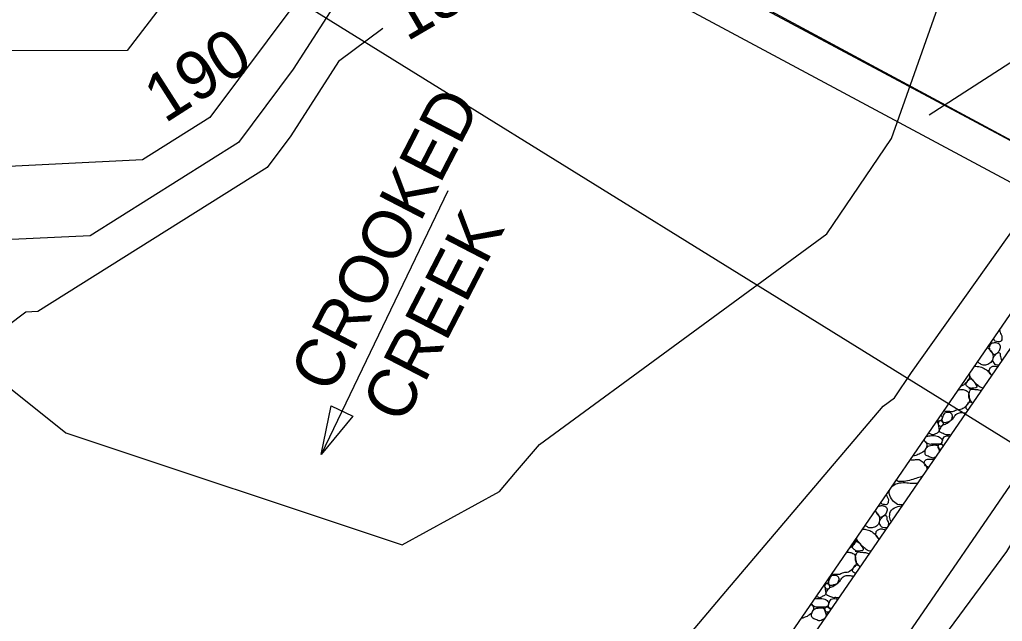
# Model space of a CAD drawing. Extents: x 1385284 to 1385995, y 1975154 to 1975620.
# Drawn here: x 1385530.9 to 1385581.7, y 1975526 to 1975557.1 of the extents above; entities that cross this region are included whole.
import ezdxf

# ---------------------------------------------------------------- set-up
doc = ezdxf.new("R2010")
doc.units = 0
for name, color, linetype in [('Default', 7, 'Continuous'), ('DTM_CONTOURS_MINOR', 7, 'Continuous'), ('R_Prop Surface', 7, 'Continuous'), ('R_Proposed Const Limits', 7, 'Continuous'), ('S_BASELINE', 7, 'Continuous'), ('S_BRIDGE', 7, 'Continuous'), ('S_UNDERGROUND_CABLE', 7, 'Continuous'), ('S_WATER_UTILITIES', 7, 'Continuous')]:
    doc.layers.add(name, color=color, linetype=linetype)

msp = doc.modelspace()

# ---------------------------------------------------------------- linework, layer by layer
at = {"layer": 'Default'}
for p, q in [((1385552.239, 1975498.351), (1385589.716, 1975552.857)), ((1385590.54, 1975552.29), (1385553.307, 1975498.139)), ((1385553.052, 1975548.241), (1385546.5, 1975534.596))]:
    msp.add_line(p, q, dxfattribs=at)
msp.add_lwpolyline([(1385548.145, 1975536.579), (1385546.5, 1975534.596), (1385547.018, 1975537.12)], close=True, dxfattribs=at)
for points in [[(1385581.715, 1975540.534), (1385581.704, 1975540.509), (1385581.656, 1975540.419), (1385581.534, 1975540.434), (1385581.355, 1975540.453), (1385581.331, 1975540.546), (1385581.303, 1975540.598), (1385581.296, 1975540.611)], [(1385581.597, 1975541.049), (1385581.6, 1975541.047), (1385581.63, 1975541.021), (1385581.615, 1975540.93), (1385581.677, 1975540.804), (1385581.759, 1975540.668), (1385581.696, 1975540.564), (1385581.715, 1975540.534)], [(1385580.975, 1975540.144), (1385581.019, 1975540.107), (1385581.16, 1975539.971), (1385581.288, 1975539.759), (1385581.25, 1975539.442), (1385581.064, 1975539.27), (1385580.895, 1975539.226), (1385580.811, 1975539.226)], [(1385581.388, 1975539.8), (1385581.357, 1975539.726), (1385581.152, 1975539.908), (1385581.05, 1975540.086), (1385581.101, 1975540.306), (1385581.265, 1975540.379), (1385581.492, 1975540.386), (1385581.682, 1975540.261), (1385581.631, 1975540.023), (1385581.518, 1975539.858), (1385581.414, 1975539.811), (1385581.388, 1975539.8)], [(1385581.557, 1975539.226), (1385581.55, 1975539.226), (1385581.493, 1975539.227), (1385581.355, 1975539.25), (1385581.317, 1975539.366), (1385581.243, 1975539.475), (1385581.282, 1975539.639), (1385581.377, 1975539.751), (1385581.454, 1975539.84), (1385581.533, 1975539.895), (1385581.658, 1975539.844), (1385581.615, 1975539.727), (1385581.676, 1975539.605), (1385581.702, 1975539.496), (1385581.712, 1975539.451)], [(1385580.305, 1975539.169), (1385580.402, 1975539.164), (1385580.602, 1975539.167), (1385580.883, 1975539.027), (1385581.071, 1975538.869), (1385581.162, 1975538.73), (1385581.186, 1975538.686)], [(1385580.811, 1975539.226), (1385580.739, 1975539.223), (1385580.603, 1975539.285), (1385580.502, 1975539.363), (1385580.462, 1975539.398)], [(1385581.187, 1975538.687), (1385581.181, 1975538.693), (1385581.118, 1975538.77), (1385581.05, 1975538.883), (1385581.101, 1975539.103), (1385581.265, 1975539.176), (1385581.42, 1975539.186), (1385581.502, 1975539.153), (1385581.506, 1975539.151)], [(1385580.035, 1975538.777), (1385580.049, 1975538.706), (1385580.077, 1975538.518), (1385579.882, 1975538.329), (1385579.736, 1975538.172), (1385579.628, 1975538.143), (1385579.595, 1975538.137)], [(1385580.736, 1975538.031), (1385580.69, 1975538.043), (1385580.54, 1975538.12), (1385580.36, 1975538.287), (1385580.156, 1975538.505), (1385580.063, 1975538.684), (1385580.031, 1975538.771)], [(1385580.128, 1975538.023), (1385580.081, 1975538.023), (1385579.985, 1975538.095), (1385579.822, 1975538.188), (1385579.931, 1975538.374), (1385579.979, 1975538.538), (1385580.16, 1975538.512), (1385580.28, 1975538.408), (1385580.347, 1975538.263), (1385580.534, 1975538.014), (1385579.784, 1975538.032), (1385580.17, 1975538.021), (1385580.162, 1975538.023)], [(1385579.459, 1975537.939), (1385579.478, 1975537.946), (1385579.589, 1975537.981), (1385579.754, 1975537.959), (1385580.017, 1975537.872), (1385580.01, 1975537.645), (1385580.096, 1975537.333), (1385579.882, 1975537.126), (1385579.66, 1975536.904), (1385579.383, 1975536.937), (1385579.147, 1975536.761), (1385578.981, 1975536.841), (1385578.902, 1975536.82)], [(1385580.208, 1975537.264), (1385580.192, 1975537.283), (1385580.111, 1975537.383), (1385579.991, 1975537.548), (1385580.024, 1975537.774), (1385580.094, 1975538.016), (1385580.323, 1975537.963), (1385580.514, 1975537.962), (1385580.64, 1975537.928), (1385580.66, 1975537.921)], [(1385579.962, 1975536.906), (1385579.924, 1975536.935), (1385579.827, 1975536.994), (1385579.931, 1975537.171), (1385579.979, 1975537.335), (1385580.137, 1975537.32), (1385580.186, 1975537.29), (1385580.211, 1975537.268)], [(1385578.564, 1975536.638), (1385578.568, 1975536.634), (1385578.624, 1975536.58), (1385578.655, 1975536.496), (1385578.559, 1975536.329), (1385578.448, 1975536.338), (1385578.382, 1975536.336), (1385578.357, 1975536.336)], [(1385578.902, 1975535.617), (1385578.83, 1975535.613), (1385578.695, 1975535.693), (1385578.435, 1975535.782), (1385578.549, 1975535.951), (1385578.628, 1975536.137), (1385578.853, 1975536.182), (1385579.053, 1975536.34), (1385579.233, 1975536.482), (1385579.327, 1975536.688), (1385579.539, 1975536.781), (1385579.723, 1975536.767), (1385579.837, 1975536.753), (1385579.854, 1975536.749)], [(1385579.045, 1975536.337), (1385578.997, 1975536.323), (1385578.901, 1975536.299), (1385578.766, 1975536.246), (1385578.64, 1975536.287), (1385578.613, 1975536.394), (1385578.643, 1975536.508), (1385578.686, 1975536.635), (1385578.747, 1975536.759), (1385578.897, 1975536.776), (1385579.069, 1975536.772), (1385579.182, 1975536.644), (1385579.158, 1975536.484), (1385579.097, 1975536.367), (1385579.045, 1975536.337)], [(1385578.902, 1975536.82), (1385578.843, 1975536.817), (1385578.784, 1975536.84), (1385578.724, 1975536.871)], [(1385578.339, 1975536.311), (1385578.346, 1975536.307), (1385578.436, 1975536.233), (1385578.432, 1975536.079), (1385578.514, 1975535.767), (1385578.33, 1975535.69), (1385578.227, 1975535.642), (1385578.178, 1975535.617)], [(1385578.617, 1975536.071), (1385578.58, 1975536.071), (1385578.495, 1975536.069), (1385578.415, 1975536.151), (1385578.424, 1975536.269), (1385578.508, 1975536.371), (1385578.635, 1975536.321), (1385578.738, 1975536.16), (1385578.651, 1975536.101), (1385578.617, 1975536.071)], [(1385577.813, 1975535.545), (1385577.839, 1975535.554), (1385578.007, 1975535.572), (1385578.297, 1975535.601), (1385578.595, 1975535.479), (1385578.655, 1975535.293), (1385578.559, 1975535.126), (1385578.353, 1975535.134), (1385578.193, 1975535.128), (1385578.073, 1975535.134)], [(1385578.178, 1975535.617), (1385578.106, 1975535.628), (1385578.02, 1975535.665), (1385577.937, 1975535.701), (1385577.924, 1975535.707)], [(1385578.697, 1975535.067), (1385578.68, 1975535.072), (1385578.631, 1975535.103), (1385578.613, 1975535.191), (1385578.643, 1975535.305), (1385578.686, 1975535.432), (1385578.747, 1975535.556), (1385578.881, 1975535.57), (1385578.976, 1975535.57), (1385579.032, 1975535.553)], [(1385579.072, 1975535.611), (1385579.014, 1975535.615), (1385578.955, 1975535.631), (1385578.902, 1975535.617)], [(1385577.678, 1975535.349), (1385577.736, 1975535.293), (1385577.899, 1975535.159), (1385577.78, 1975534.82), (1385577.491, 1975534.63), (1385577.271, 1975534.558), (1385577.112, 1975534.514), (1385577.102, 1975534.511)], [(1385578.073, 1975535.134), (1385578.018, 1975535.111), (1385577.873, 1975535.168), (1385577.73, 1975535.248), (1385577.702, 1975535.354), (1385577.704, 1975535.386)], [(1385578.178, 1975534.414), (1385578.106, 1975534.425), (1385577.962, 1975534.494), (1385577.739, 1975534.564), (1385577.741, 1975534.793), (1385577.852, 1975535.038), (1385578.067, 1975535.088), (1385578.429, 1975535.117), (1385578.44, 1975534.917), (1385578.483, 1975534.794), (1385578.491, 1975534.767)], [(1385578.562, 1975534.87), (1385578.543, 1975534.872), (1385578.483, 1975534.881), (1385578.415, 1975534.948), (1385578.424, 1975535.066), (1385578.508, 1975535.168), (1385578.613, 1975535.129), (1385578.676, 1975535.071), (1385578.69, 1975535.056)], [(1385578.285, 1975534.466), (1385578.249, 1975534.449), (1385578.214, 1975534.432), (1385578.178, 1975534.414)], [(1385576.985, 1975534.341), (1385577.046, 1975534.336), (1385577.191, 1975534.313), (1385577.45, 1975534.387), (1385577.653, 1975534.181), (1385577.83, 1975534.017), (1385577.845, 1975533.87), (1385577.838, 1975533.817)], [(1385577.928, 1975533.947), (1385577.915, 1975533.953), (1385577.836, 1975533.99), (1385577.711, 1975534.052), (1385577.701, 1975534.218), (1385577.778, 1975534.35), (1385577.963, 1975534.364), (1385578.108, 1975534.373), (1385578.216, 1975534.366)], [(1385577.608, 1975533.483), (1385577.595, 1975533.475), (1385577.437, 1975533.409), (1385577.123, 1975533.326), (1385576.751, 1975533.198), (1385576.518, 1975533.212), (1385576.446, 1975533.215)], [(1385576.004, 1975532.914), (1385576.094, 1975533.017), (1385576.317, 1975533.138), (1385576.724, 1975533.163), (1385577.065, 1975533.1), (1385577.3, 1975533.131), (1385577.366, 1975533.13)], [(1385576.446, 1975533.215), (1385576.389, 1975533.187), (1385576.313, 1975533.223), (1385576.248, 1975533.269)], [(1385575.742, 1975532.533), (1385575.763, 1975532.478), (1385575.809, 1975532.378), (1385575.89, 1975532.247), (1385575.827, 1975532.144), (1385575.845, 1975532.114)], [(1385576.446, 1975532.012), (1385576.378, 1975531.978), (1385576.155, 1975532.116), (1385575.951, 1975532.35), (1385575.864, 1975532.662), (1385575.921, 1975532.794)], [(1385575.317, 1975531.915), (1385575.337, 1975531.924), (1385575.434, 1975531.961), (1385575.623, 1975531.965), (1385575.813, 1975531.84), (1385575.761, 1975531.602), (1385575.648, 1975531.437), (1385575.545, 1975531.39), (1385575.519, 1975531.379)], [(1385575.845, 1975532.114), (1385575.835, 1975532.089), (1385575.787, 1975531.999), (1385575.664, 1975532.013), (1385575.505, 1975532.026), (1385575.475, 1975532.096), (1385575.461, 1975532.125)], [(1385575.996, 1975531.138), (1385575.991, 1975531.147), (1385575.906, 1975531.293), (1385575.91, 1975531.676), (1385576.253, 1975531.916), (1385576.486, 1975531.952), (1385576.559, 1975531.956)], [(1385576.594, 1975532.007), (1385576.544, 1975532.007), (1385576.495, 1975532.01), (1385576.446, 1975532.012)], [(1385575.155, 1975531.679), (1385575.18, 1975531.654), (1385575.3, 1975531.53), (1385575.418, 1975531.338), (1385575.38, 1975531.021), (1385575.194, 1975530.849), (1385575.026, 1975530.805), (1385574.941, 1975530.806)], [(1385575.519, 1975531.379), (1385575.488, 1975531.305), (1385575.283, 1975531.487), (1385575.203, 1975531.638), (1385575.194, 1975531.725), (1385575.194, 1975531.736)], [(1385575.777, 1975530.819), (1385575.74, 1975530.801), (1385575.654, 1975530.809), (1385575.486, 1975530.829), (1385575.448, 1975530.946), (1385575.374, 1975531.054), (1385575.413, 1975531.218), (1385575.507, 1975531.33), (1385575.584, 1975531.419), (1385575.664, 1975531.475), (1385575.789, 1975531.424), (1385575.746, 1975531.307), (1385575.808, 1975531.181), (1385575.887, 1975531.046), (1385575.829, 1975530.945), (1385575.843, 1975530.915)], [(1385574.941, 1975530.806), (1385574.87, 1975530.802), (1385574.76, 1975530.852), (1385574.669, 1975530.915), (1385574.643, 1975530.936)], [(1385574.512, 1975530.744), (1385574.584, 1975530.74), (1385574.755, 1975530.735), (1385575.013, 1975530.606), (1385575.226, 1975530.429), (1385575.32, 1975530.266), (1385575.349, 1975530.197)], [(1385575.364, 1975530.219), (1385575.34, 1975530.241), (1385575.257, 1975530.335), (1385575.181, 1975530.462), (1385575.232, 1975530.682), (1385575.396, 1975530.755), (1385575.577, 1975530.764), (1385575.672, 1975530.713), (1385575.693, 1975530.698)], [(1385574.181, 1975530.263), (1385574.185, 1975530.224), (1385574.184, 1975530.075), (1385574.013, 1975529.909), (1385573.896, 1975529.777), (1385573.825, 1975529.746)], [(1385574.259, 1975529.603), (1385574.212, 1975529.602), (1385574.116, 1975529.674), (1385573.953, 1975529.768), (1385574.062, 1975529.953), (1385574.11, 1975530.117), (1385574.291, 1975530.091), (1385574.41, 1975529.987), (1385574.477, 1975529.842), (1385574.664, 1975529.594), (1385573.915, 1975529.611), (1385574.301, 1975529.6), (1385574.293, 1975529.603)], [(1385574.94, 1975529.603), (1385574.869, 1975529.6), (1385574.687, 1975529.684), (1385574.491, 1975529.866), (1385574.307, 1975530.064), (1385574.218, 1975530.217), (1385574.191, 1975530.278)], [(1385573.687, 1975529.544), (1385573.768, 1975529.558), (1385573.899, 1975529.537), (1385574.148, 1975529.452), (1385574.14, 1975529.224), (1385574.226, 1975528.913), (1385574.012, 1975528.705), (1385573.79, 1975528.483), (1385573.514, 1975528.516), (1385573.277, 1975528.34), (1385573.112, 1975528.42), (1385573.033, 1975528.4)], [(1385574.382, 1975528.79), (1385574.351, 1975528.826), (1385574.252, 1975528.943), (1385574.122, 1975529.127), (1385574.154, 1975529.353), (1385574.225, 1975529.595), (1385574.454, 1975529.542), (1385574.671, 1975529.543), (1385574.813, 1975529.494), (1385574.853, 1975529.476)], [(1385574.146, 1975528.447), (1385574.135, 1975528.455), (1385574.078, 1975528.497), (1385573.953, 1975528.565), (1385574.062, 1975528.75), (1385574.11, 1975528.914), (1385574.287, 1975528.89), (1385574.354, 1975528.844), (1385574.387, 1975528.797)], [(1385573.033, 1975528.4), (1385572.994, 1975528.397), (1385572.955, 1975528.407), (1385572.915, 1975528.422)], [(1385572.748, 1975527.65), (1385572.71, 1975527.651), (1385572.626, 1975527.648), (1385572.546, 1975527.73), (1385572.554, 1975527.848), (1385572.638, 1975527.95), (1385572.766, 1975527.9), (1385572.869, 1975527.739), (1385572.781, 1975527.68), (1385572.748, 1975527.65)], [(1385572.738, 1975528.164), (1385572.763, 1975528.121), (1385572.777, 1975528.054), (1385572.691, 1975527.909), (1385572.606, 1975527.917), (1385572.568, 1975527.917)], [(1385573.033, 1975527.197), (1385572.961, 1975527.192), (1385572.826, 1975527.272), (1385572.566, 1975527.361), (1385572.68, 1975527.53), (1385572.759, 1975527.717), (1385572.984, 1975527.761), (1385573.184, 1975527.919), (1385573.363, 1975528.061), (1385573.458, 1975528.267), (1385573.67, 1975528.36), (1385573.874, 1975528.339), (1385574.013, 1975528.327), (1385574.048, 1975528.305)], [(1385573.175, 1975527.917), (1385573.128, 1975527.902), (1385573.032, 1975527.878), (1385572.897, 1975527.825), (1385572.771, 1975527.866), (1385572.743, 1975527.973), (1385572.774, 1975528.087), (1385572.817, 1975528.214), (1385572.878, 1975528.338), (1385573.028, 1975528.355), (1385573.2, 1975528.351), (1385573.313, 1975528.224), (1385573.289, 1975528.063), (1385573.228, 1975527.946), (1385573.175, 1975527.917)], [(1385572.518, 1975527.845), (1385572.57, 1975527.78), (1385572.571, 1975527.641), (1385572.645, 1975527.346), (1385572.46, 1975527.269), (1385572.357, 1975527.221), (1385572.309, 1975527.197)], [(1385571.855, 1975526.88), (1385571.893, 1975526.838), (1385572.022, 1975526.711), (1385571.91, 1975526.399), (1385571.644, 1975526.219), (1385571.455, 1975526.154), (1385571.331, 1975526.118)], [(1385572.204, 1975526.714), (1385572.149, 1975526.69), (1385572.004, 1975526.747), (1385571.901, 1975526.814), (1385571.858, 1975526.878), (1385571.856, 1975526.881)], [(1385572.032, 1975527.138), (1385572.171, 1975527.152), (1385572.43, 1975527.179), (1385572.726, 1975527.058), (1385572.785, 1975526.872), (1385572.69, 1975526.705), (1385572.484, 1975526.713), (1385572.324, 1975526.707), (1385572.204, 1975526.714)], [(1385572.309, 1975527.197), (1385572.244, 1975527.206), (1385572.18, 1975527.231), (1385572.115, 1975527.259)], [(1385572.908, 1975526.647), (1385572.901, 1975526.645), (1385572.857, 1975526.633), (1385572.771, 1975526.663), (1385572.743, 1975526.77), (1385572.774, 1975526.884), (1385572.817, 1975527.011), (1385572.878, 1975527.135), (1385573.028, 1975527.152), (1385573.148, 1975527.148), (1385573.22, 1975527.107), (1385573.223, 1975527.105)], [(1385573.287, 1975527.197), (1385573.286, 1975527.197), (1385573.206, 1975527.171), (1385573.112, 1975527.217), (1385573.033, 1975527.197)], [(1385572.309, 1975525.994), (1385572.237, 1975526.004), (1385572.093, 1975526.073), (1385571.869, 1975526.143), (1385571.872, 1975526.372), (1385571.982, 1975526.617), (1385572.198, 1975526.667), (1385572.56, 1975526.696), (1385572.568, 1975526.479), (1385572.636, 1975526.314), (1385572.642, 1975526.259)], [(1385572.748, 1975526.447), (1385572.71, 1975526.448), (1385572.626, 1975526.446), (1385572.546, 1975526.527), (1385572.554, 1975526.645), (1385572.638, 1975526.747), (1385572.755, 1975526.702), (1385572.848, 1975526.61), (1385572.86, 1975526.577)], [(1385572.639, 1975526.255), (1385572.646, 1975526.276), (1385572.685, 1975526.343), (1385572.719, 1975526.431), (1385572.777, 1975526.471), (1385572.793, 1975526.48)], [(1385572.8, 1975526.49), (1385572.782, 1975526.476), (1385572.764, 1975526.462), (1385572.748, 1975526.447)], [(1385572.534, 1975526.103), (1385572.509, 1975526.09), (1385572.433, 1975526.053), (1385572.357, 1975526.018), (1385572.309, 1975525.994)]]:
    msp.add_open_spline(points, degree=3, dxfattribs=at)
at = {"layer": 'DTM_CONTOURS_MINOR'}
for points in [[(1385566.44, 1975607.406), (1385566.403, 1975602.698), (1385564.907, 1975594.54), (1385562.955, 1975591.481), (1385558.587, 1975584.007), (1385555.274, 1975578.535), (1385551.48, 1975572.062), (1385547.571, 1975565.618), (1385548.146, 1975562.577), (1385545.187, 1975557.988), (1385540.742, 1975552.033), (1385537.252, 1975549.84), (1385528.237, 1975549.401), (1385522.764, 1975545.306), (1385513.238, 1975549.849), (1385506.531, 1975552.582), (1385500.268, 1975555.138), (1385492.923, 1975560.68)], [(1385576.008, 1975550.943), (1385580.588, 1975563.887), (1385581.058, 1975564.95), (1385581.405, 1975566.194), (1385580.618, 1975567.697), (1385574.401, 1975574.905), (1385577.08, 1975585.604), (1385578.005, 1975594.781), (1385572.58, 1975593.033), (1385572.44, 1975587.743), (1385565.345, 1975575.891), (1385564.229, 1975574.049), (1385562.885, 1975571.835), (1385555.987, 1975560.294), (1385554.873, 1975559.657)], [(1385562.866, 1975481.018), (1385563.716, 1975498.339), (1385566.287, 1975500.31), (1385572.546, 1975503.642), (1385585.482, 1975508.711), (1385572.018, 1975516.132), (1385577.884, 1975524.056), (1385581.986, 1975529.59), (1385586.864, 1975537.76), (1385589.378, 1975541.298), (1385592.421, 1975550.843), (1385595.925, 1975556.919), (1385603.651, 1975570.298), (1385603.747, 1975570.566), (1385603.842, 1975570.633), (1385603.931, 1975570.594), (1385610.734, 1975574.084), (1385616.057, 1975580.707), (1385617.625, 1975582.015), (1385623.884, 1975585.062), (1385632.559, 1975588.36), (1385643.399, 1975583.605), (1385645.132, 1975583.412)], [(1385562.295, 1975581.809), (1385559.199, 1975576.702), (1385551.832, 1975564.557), (1385551.357, 1975563.762), (1385550.942, 1975563.524), (1385550.765, 1975563.392), (1385545.057, 1975554.541), (1385542.221, 1975550.741), (1385534.545, 1975545.92), (1385529.729, 1975545.685)], [(1385540.333, 1975560.553), (1385536.466, 1975555.492), (1385527.883, 1975555.491)], [(1385549.689, 1975556.641), (1385547.397, 1975554.924), (1385544.926, 1975551.094), (1385543.699, 1975549.449), (1385531.839, 1975541.999), (1385531.221, 1975541.969), (1385528.247, 1975539.743), (1385533.287, 1975535.725), (1385550.692, 1975529.929), (1385555.732, 1975532.693), (1385556.564, 1975533.677), (1385557.793, 1975535.126), (1385572.665, 1975546.009), (1385576.008, 1975550.943)], [(1385545.652, 1975507.742), (1385547.007, 1975511.231), (1385551.272, 1975515.155), (1385561.935, 1975521), (1385567.445, 1975527.513), (1385575.575, 1975537.104), (1385576.161, 1975537.532), (1385577.055, 1975538.851), (1385583.12, 1975547.386)]]:
    msp.add_lwpolyline(points, dxfattribs=at)
at = {"layer": 'R_Prop Surface'}
msp.add_line((1385577.955, 1975552.175), (1385603.086, 1975568.344), dxfattribs=at)
at = {"layer": 'R_Proposed Const Limits'}
msp.add_line((1385593.836, 1975550.024), (1385551.164, 1975487.962), dxfattribs=at)
at = {"layer": 'S_BASELINE'}
msp.add_line((1385476.399, 1975607.406), (1385611.25, 1975535.294), dxfattribs=at)
at = {"layer": 'S_BRIDGE'}
msp.add_line((1385600.863, 1975540.79), (1385540.376, 1975573.382), dxfattribs=at)
at = {"layer": 'S_UNDERGROUND_CABLE'}
msp.add_line((1385526.194, 1975569.941), (1385618.813, 1975512.534), dxfattribs=at)
at = {"layer": 'S_WATER_UTILITIES'}
msp.add_line((1385542.172, 1975570.138), (1385595.728, 1975541.409), dxfattribs=at)

# ---------------------------------------------------------------- texts
at = {"layer": 'Default'}
for s, rotation, p in [('187', 30.1914, (1385550.932, 1975555.941)), ('190', 32.6128, (1385538.408, 1975551.7)), ('CROOKED', 62.6215, (1385547.005, 1975537.66)), ('CREEK', 62.6215, (1385550.732, 1975536.09))]:
    msp.add_text(s, height=2.5, rotation=rotation, dxfattribs=at).set_placement(p)

doc.saveas('drawing.dxf')
